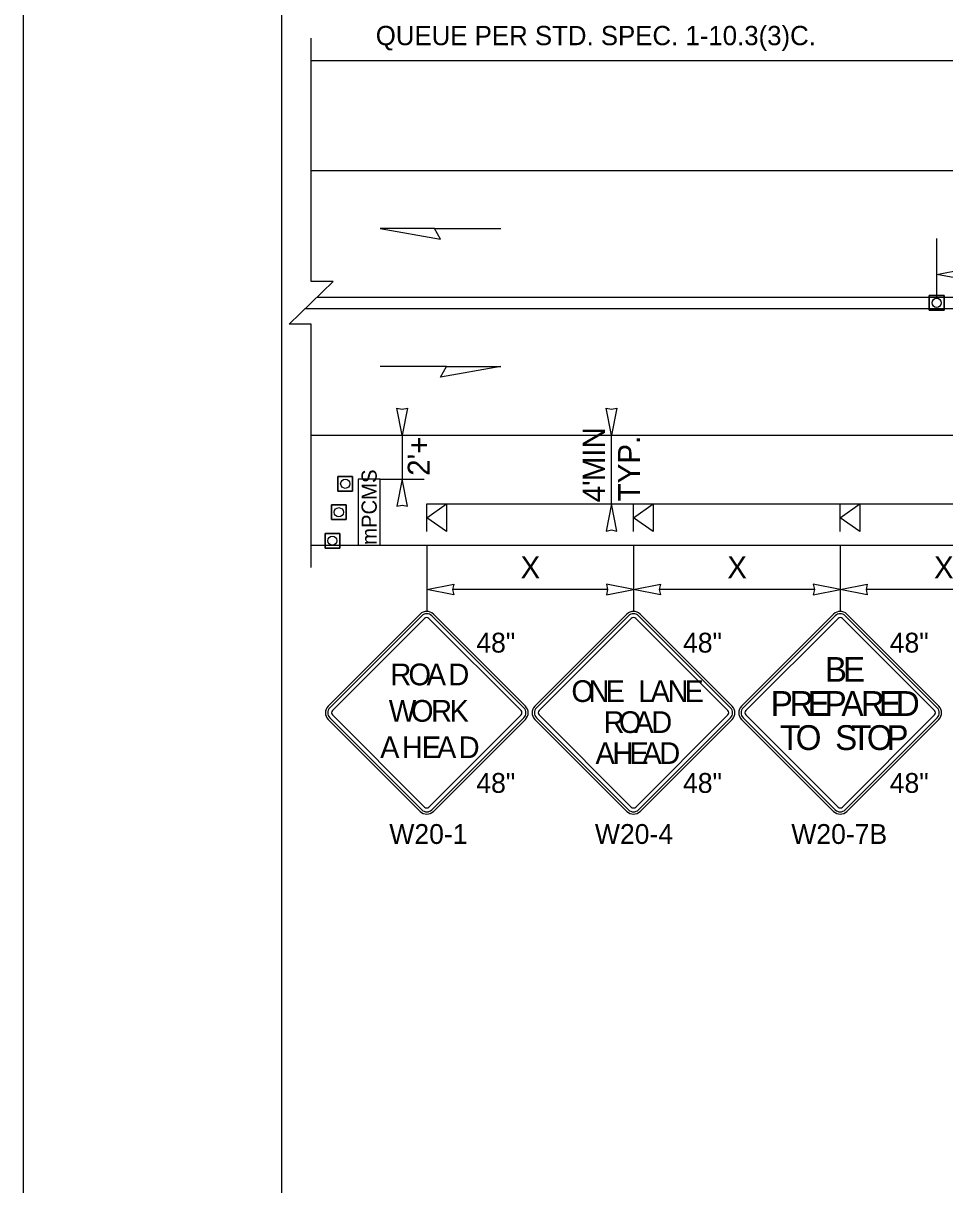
# Model space of a CAD drawing. Extents: x 99999.1 to 100095.7, y 99995 to 100010.7.
# Drawn here: x 100039.062 to 100042.406, y 100003.412 to 100007.627 of the extents above; entities that cross this region are included whole.
import ezdxf

# ---------------------------------------------------------------- set-up
doc = ezdxf.new("R2010")
doc.units = 0
for name, color, linetype in [('RD_ED_ShoulderPavedEdge', 7, 'Continuous'), ('RD_MK_LineDblYellowCenter', 7, 'Continuous'), ('RD_MK_LineEdgeWhite', 7, 'Continuous'), ('SH_GI_PlotLimits', 7, 'Continuous'), ('SH_GI_SheetBorder', 7, 'Continuous'), ('TR_SN_ConstructionSigns', 7, 'Continuous'), ('TR_WZ_PCMS', 7, 'Continuous'), ('TR_WZ_PortableChangeMessageSign', 7, 'Continuous'), ('TR_WZ_PortableSignMountBlk-Org', 7, 'Continuous'), ('TR_WZ_TrafficCone', 7, 'Continuous'), ('TR_WZ_WorkZoneDetails', 7, 'Continuous'), ('TR_WZ_WorkZoneTextCurrent', 7, 'Continuous')]:
    doc.layers.add(name, color=color, linetype=linetype)

msp = doc.modelspace()

# ---------------------------------------------------------------- linework, layer by layer
at = {"layer": 'RD_ED_ShoulderPavedEdge'}
for p, q in [((100040.1076, 100007.4923), (100055.6424, 100007.4923)), ((100040.1076, 100005.7323), (100055.6424, 100005.7323))]:
    msp.add_line(p, q, dxfattribs=at)
at = {"layer": 'RD_MK_LineDblYellowCenter'}
for p, q in [((100040.1282, 100006.6323), (100043.4767, 100006.6323)), ((100040.0869, 100006.5923), (100043.4767, 100006.5923))]:
    msp.add_line(p, q, dxfattribs=at)
at = {"layer": 'RD_MK_LineEdgeWhite'}
for p, q in [((100040.1076, 100007.0923), (100055.6424, 100007.0923)), ((100040.1076, 100006.1323), (100055.6424, 100006.1323))]:
    msp.add_line(p, q, dxfattribs=at)
at = {"layer": 'SH_GI_PlotLimits'}
msp.add_lwpolyline([(100039.0625, 99999.6875), (100056.0625, 99999.6875), (100056.0625, 100010.6875), (100039.0625, 100010.6875)], close=True, dxfattribs=at)
at = {"layer": 'SH_GI_SheetBorder'}
msp.add_line((100040, 100010.375), (100040, 100000), dxfattribs=at)
at = {"layer": 'TR_SN_ConstructionSigns'}
for p, q in [((100040.5028, 100005.4824), (100040.1687, 100005.1483)), ((100040.5088, 100005.4765), (100040.1746, 100005.1424)), ((100040.1846, 100005.1324), (100040.5187, 100005.4665)), ((100040.5346, 100005.4665), (100040.8687, 100005.1324)), ((100040.8787, 100005.1424), (100040.5445, 100005.4765)), ((100040.8846, 100005.1483), (100040.5505, 100005.4824)), ((100041.2528, 100005.4824), (100040.9187, 100005.1483)), ((100041.2588, 100005.4765), (100040.9246, 100005.1424)), ((100040.9346, 100005.1324), (100041.2687, 100005.4665)), ((100041.2846, 100005.4665), (100041.6187, 100005.1324)), ((100041.6287, 100005.1424), (100041.2945, 100005.4765)), ((100041.6346, 100005.1483), (100041.3005, 100005.4824)), ((100042.0028, 100005.4824), (100041.6687, 100005.1483)), ((100042.0088, 100005.4765), (100041.6746, 100005.1424)), ((100041.6846, 100005.1324), (100042.0187, 100005.4665)), ((100042.0346, 100005.4665), (100042.3687, 100005.1324)), ((100042.3787, 100005.1424), (100042.0445, 100005.4765)), ((100042.3846, 100005.1483), (100042.0505, 100005.4824)), ((100040.1746, 100005.1066), (100040.5088, 100004.7725)), ((100040.5187, 100004.7824), (100040.1846, 100005.1165)), ((100040.8687, 100005.1165), (100040.5346, 100004.7824)), ((100040.5445, 100004.7725), (100040.8787, 100005.1066)), ((100040.9246, 100005.1066), (100041.2588, 100004.7725)), ((100041.2687, 100004.7824), (100040.9346, 100005.1165)), ((100041.6187, 100005.1165), (100041.2846, 100004.7824)), ((100041.2945, 100004.7725), (100041.6287, 100005.1066)), ((100041.6746, 100005.1066), (100042.0088, 100004.7725)), ((100042.0187, 100004.7824), (100041.6846, 100005.1165)), ((100042.3687, 100005.1165), (100042.0346, 100004.7824)), ((100042.0445, 100004.7725), (100042.3787, 100005.1066)), ((100040.1687, 100005.1006), (100040.5028, 100004.7665)), ((100040.5505, 100004.7665), (100040.8846, 100005.1006)), ((100040.9187, 100005.1006), (100041.2528, 100004.7665)), ((100041.3005, 100004.7665), (100041.6346, 100005.1006)), ((100041.6687, 100005.1006), (100042.0028, 100004.7665)), ((100042.0505, 100004.7665), (100042.3846, 100005.1006))]:
    msp.add_line(p, q, dxfattribs=at)
for centre, radius, start, end in [((100040.5267, 100005.4586), 0.0338, 45, 135), ((100041.2767, 100005.4586), 0.0338, 45, 135), ((100042.0267, 100005.4586), 0.0338, 45, 135), ((100040.5267, 100005.4586), 0.0253, 45, 135), ((100040.5267, 100005.4586), 0.0113, 45, 135), ((100041.2767, 100005.4586), 0.0253, 45, 135), ((100041.2767, 100005.4586), 0.0113, 45, 135), ((100042.0267, 100005.4586), 0.0253, 45, 135), ((100042.0267, 100005.4586), 0.0113, 45, 135), ((100040.1925, 100005.1245), 0.0338, 135, 225), ((100040.8608, 100005.1245), 0.0338, 315, 45), ((100040.9425, 100005.1245), 0.0338, 135, 225), ((100041.6108, 100005.1245), 0.0338, 315, 45), ((100041.6925, 100005.1245), 0.0338, 135, 225), ((100042.3608, 100005.1245), 0.0338, 315, 45), ((100040.1925, 100005.1245), 0.0253, 135, 225), ((100040.1925, 100005.1245), 0.0113, 135, 225), ((100040.8608, 100005.1245), 0.0113, 315, 45), ((100040.8608, 100005.1245), 0.0253, 315, 45), ((100040.9425, 100005.1245), 0.0253, 135, 225), ((100040.9425, 100005.1245), 0.0113, 135, 225), ((100041.6108, 100005.1245), 0.0113, 315, 45), ((100041.6108, 100005.1245), 0.0253, 315, 45), ((100041.6925, 100005.1245), 0.0253, 135, 225), ((100041.6925, 100005.1245), 0.0113, 135, 225), ((100042.3608, 100005.1245), 0.0113, 315, 45), ((100042.3608, 100005.1245), 0.0253, 315, 45), ((100040.5267, 100004.7904), 0.0253, 225, 315), ((100040.5267, 100004.7904), 0.0113, 225, 315), ((100041.2767, 100004.7904), 0.0253, 225, 315), ((100041.2767, 100004.7904), 0.0113, 225, 315), ((100042.0267, 100004.7904), 0.0253, 225, 315), ((100042.0267, 100004.7904), 0.0113, 225, 315), ((100040.5267, 100004.7904), 0.0338, 225, 315), ((100041.2767, 100004.7904), 0.0338, 225, 315), ((100042.0267, 100004.7904), 0.0338, 225, 315)]:
    msp.add_arc(centre, radius, start, end, dxfattribs=at)
at = {"layer": 'TR_WZ_PCMS'}
msp.add_lwpolyline([(100040.3576, 100005.7323), (100040.3576, 100005.9723), (100040.2776, 100005.9723), (100040.2776, 100005.7323)], close=True, dxfattribs=at)
msp.add_lwpolyline([(100040.3576, 100005.7323), (100040.3576, 100005.9723), (100040.2776, 100005.9723), (100040.2776, 100005.7323), (100040.3576, 100005.7323)], dxfattribs=at)
at = {"layer": 'TR_WZ_PortableSignMountBlk-Org'}
for p, q in [((100040.5267, 100005.7824), (100040.5267, 100005.8824)), ((100041.2767, 100005.7824), (100041.2767, 100005.8824)), ((100042.0267, 100005.7824), (100042.0267, 100005.8824))]:
    msp.add_line(p, q, dxfattribs=at)
for points in [[(100040.5267, 100005.8323), (100040.5985, 100005.8824), (100040.5985, 100005.7824)], [(100041.2767, 100005.8323), (100041.3485, 100005.8824), (100041.3485, 100005.7824)], [(100042.0267, 100005.8323), (100042.0985, 100005.8824), (100042.0985, 100005.7824)]]:
    msp.add_lwpolyline(points, close=True, dxfattribs=at)
at = {"layer": 'TR_WZ_TrafficCone'}
for points in [[(100042.4033, 100006.639), (100042.35, 100006.639), (100042.35, 100006.5857), (100042.4033, 100006.5857), (100042.4033, 100006.639)], [(100042.4033, 100006.5857), (100042.35, 100006.5857), (100042.35, 100006.639), (100042.4033, 100006.639), (100042.4033, 100006.5857)], [(100040.2042, 100005.9823), (100040.2576, 100005.9823), (100040.2576, 100005.929), (100040.2042, 100005.929), (100040.2042, 100005.9823)], [(100040.2042, 100005.929), (100040.2576, 100005.929), (100040.2576, 100005.9823), (100040.2042, 100005.9823), (100040.2042, 100005.929)], [(100040.1809, 100005.879), (100040.2342, 100005.879), (100040.2342, 100005.8257), (100040.1809, 100005.8257), (100040.1809, 100005.879)], [(100040.1809, 100005.8257), (100040.2342, 100005.8257), (100040.2342, 100005.879), (100040.1809, 100005.879), (100040.1809, 100005.8257)], [(100040.1576, 100005.7757), (100040.2109, 100005.7757), (100040.2109, 100005.7223), (100040.1576, 100005.7223), (100040.1576, 100005.7757)], [(100040.1576, 100005.7223), (100040.2109, 100005.7223), (100040.2109, 100005.7757), (100040.1576, 100005.7757), (100040.1576, 100005.7223)]]:
    msp.add_lwpolyline(points, dxfattribs=at)
for centre in [(100042.3767, 100006.6123), (100040.2309, 100005.9557), (100040.2076, 100005.8523), (100040.1842, 100005.749)]:
    msp.add_circle(centre, 0.0167, dxfattribs=at)
at = {"layer": 'TR_WZ_WorkZoneDetails'}
for p, q in [((100040.5541, 100006.8816), (100040.7952, 100006.8816)), ((100042.3767, 100006.6357), (100042.3767, 100006.8457)), ((100040.5987, 100006.3816), (100040.3576, 100006.3816)), ((100040.3576, 100006.1323), (100040.5176, 100006.1323)), ((100040.4376, 100006.1323), (100040.4376, 100005.9723)), ((100041.1167, 100006.1323), (100041.2767, 100006.1323)), ((100041.1967, 100005.8824), (100041.1967, 100006.1323)), ((100040.3576, 100005.9723), (100040.5176, 100005.9723)), ((100040.5267, 100005.8824), (100043.5267, 100005.8824)), ((100041.1167, 100005.8824), (100041.2767, 100005.8824)), ((100040.5267, 100005.7326), (100040.5267, 100005.4923)), ((100041.2767, 100005.7323), (100041.2767, 100005.4923)), ((100042.0267, 100005.7323), (100042.0267, 100005.4923)), ((100041.1829, 100005.5723), (100040.6204, 100005.5723)), ((100041.9329, 100005.5723), (100041.3704, 100005.5723)), ((100042.6829, 100005.5723), (100042.1204, 100005.5723))]:
    msp.add_line(p, q, dxfattribs=at)
msp.add_lwpolyline([(100040.1076, 100005.6523), (100040.1076, 100006.5349), (100040.0275, 100006.5349), (100040.1876, 100006.6898), (100040.1076, 100006.6898), (100040.1076, 100007.5723)], dxfattribs=at)
for points in [[(100040.3576, 100006.8816), (100040.5764, 100006.843), (100040.5541, 100006.8816)], [(100042.3767, 100006.7157), (100042.4749, 100006.7349), (100042.4704, 100006.7157), (100042.4749, 100006.6964)], [(100040.7952, 100006.3816), (100040.5764, 100006.343), (100040.5987, 100006.3816)], [(100040.4376, 100006.1323), (100040.4183, 100006.2306), (100040.4376, 100006.2261), (100040.4568, 100006.2306)], [(100041.1967, 100006.1323), (100041.1774, 100006.2306), (100041.1967, 100006.2261), (100041.2159, 100006.2306)], [(100040.4376, 100005.9723), (100040.4183, 100005.8741), (100040.4376, 100005.8786), (100040.4568, 100005.8741)], [(100041.1967, 100005.8824), (100041.1774, 100005.7841), (100041.1967, 100005.7887), (100041.2159, 100005.7841)], [(100040.5267, 100005.5723), (100040.6249, 100005.5916), (100040.6204, 100005.5723), (100040.6249, 100005.5531)], [(100041.2767, 100005.5723), (100041.1784, 100005.5916), (100041.1829, 100005.5723), (100041.1784, 100005.5531)], [(100041.2767, 100005.5723), (100041.3749, 100005.5916), (100041.3704, 100005.5723), (100041.3749, 100005.5531)], [(100042.0267, 100005.5723), (100041.9284, 100005.5916), (100041.9329, 100005.5723), (100041.9284, 100005.5531)], [(100042.0267, 100005.5723), (100042.1249, 100005.5916), (100042.1204, 100005.5723), (100042.1249, 100005.5531)]]:
    msp.add_lwpolyline(points, close=True, dxfattribs=at)

# ---------------------------------------------------------------- texts
at = {"layer": 'TR_SN_ConstructionSigns'}
for s, p in [('48"', (100040.7064, 100005.343)), ('48"', (100041.4564, 100005.343)), ('48"', (100042.2064, 100005.343)), ('48"', (100040.7064, 100004.8339)), ('48"', (100041.4564, 100004.8339)), ('48"', (100042.2064, 100004.8339)), ('W20-1', (100040.3908, 100004.6486)), ('W20-4', (100041.1367, 100004.6486)), ('W20-7B', (100041.8493, 100004.6486))]:
    msp.add_text(s, height=0.072, rotation=360, dxfattribs=at).set_placement(p)
for s, height, p in [('B', 0.09, (100041.9709, 100005.237)), ('E', 0.09, (100042.0366, 100005.237)), ('R', 0.0788, (100040.3947, 100005.2243)), ('O', 0.0788, (100040.4601, 100005.2243)), ('A', 0.0788, (100040.5263, 100005.2243)), ('D', 0.0788, (100040.605, 100005.2243)), ('O', 0.0787, (100041.0514, 100005.1638)), ('N', 0.0787, (100041.1136, 100005.1638)), ('E', 0.0787, (100041.1751, 100005.1638)), ('L', 0.0787, (100041.294, 100005.1638)), ('A', 0.0787, (100041.3389, 100005.1638)), ('N', 0.0787, (100041.4003, 100005.1638)), ('E', 0.0787, (100041.4617, 100005.1638)), ('P', 0.09, (100041.7747, 100005.1132)), ('R', 0.09, (100041.8431, 100005.1132)), ('E', 0.09, (100041.9088, 100005.1132)), ('P', 0.09, (100041.97, 100005.1132)), ('A', 0.09, (100042.0312, 100005.1132)), ('R', 0.09, (100042.1014, 100005.1132)), ('E', 0.09, (100042.1671, 100005.1132)), ('D', 0.09, (100042.2283, 100005.1132)), ('W', 0.0788, (100040.3888, 100005.0921)), ('O', 0.0788, (100040.4692, 100005.0921)), ('R', 0.0788, (100040.5424, 100005.0921)), ('K', 0.0788, (100040.6093, 100005.0921)), ('R', 0.0787, (100041.168, 100005.0513)), ('O', 0.0787, (100041.2239, 100005.0513)), ('A', 0.0787, (100041.2798, 100005.0513)), ('D', 0.0787, (100041.3412, 100005.0513)), ('T', 0.09, (100041.8084, 100004.9895)), ('O', 0.09, (100041.8651, 100004.9895)), ('S', 0.09, (100042.0082, 100004.9895)), ('T', 0.09, (100042.0667, 100004.9895)), ('O', 0.09, (100042.1234, 100004.9895)), ('P', 0.09, (100042.1945, 100004.9895)), ('A', 0.0788, (100040.3573, 100004.9599)), ('H', 0.0788, (100040.4361, 100004.9599)), ('E', 0.0788, (100040.5085, 100004.9599)), ('A', 0.0788, (100040.5637, 100004.9599)), ('D', 0.0788, (100040.6424, 100004.9599)), ('A', 0.0787, (100041.1388, 100004.9388)), ('H', 0.0787, (100041.2003, 100004.9388)), ('E', 0.0787, (100041.2617, 100004.9388)), ('A', 0.0787, (100041.3089, 100004.9388)), ('D', 0.0787, (100041.3704, 100004.9388))]:
    msp.add_text(s, height=height, dxfattribs=at).set_placement(p)
at = {"layer": 'TR_WZ_PCMS'}
msp.add_text('mPCMS', height=0.055, rotation=90, dxfattribs=at).set_placement((100040.3451, 100005.7338))
at = {"layer": 'TR_WZ_PortableChangeMessageSign'}
msp.add_text('QUEUE PER STD. SPEC. 1-10.3(3)C.', height=0.07, rotation=360, dxfattribs=at).set_placement((100040.3416, 100007.5473))
at = {"layer": 'TR_WZ_WorkZoneTextCurrent'}
for s, rotation, p in [("2'+", 90, (100040.5376, 100005.9846)), ('MIN', 90, (100041.1727, 100005.9648)), ('TYP.', 90, (100041.3007, 100005.892)), ("4'", 90, (100041.1727, 100005.8883)), ('X', 360, (100040.8669, 100005.6123)), ('X', 360, (100041.6169, 100005.6123)), ('X', 360, (100042.3669, 100005.6123))]:
    msp.add_text(s, height=0.08, rotation=rotation, dxfattribs=at).set_placement(p)

doc.saveas('drawing.dxf')
